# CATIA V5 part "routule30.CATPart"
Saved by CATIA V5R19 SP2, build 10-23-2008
Part number: routule30
Bounding box of the stored display mesh (mm): x 0 to 16, y -31 to 31, z -31 to 31
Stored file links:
  D:\SCHOOL\FRANCE\BANC_POUTRE_EN_MOUSSE\routule30.CATPart
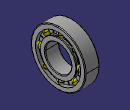
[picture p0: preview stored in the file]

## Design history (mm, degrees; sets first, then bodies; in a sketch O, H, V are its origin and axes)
Body1 "7" (main body)
  Solid1: solid without history
Body2 "6"
  Solid2: solid without history
Body3 "9"
  Solid3: solid without history
Body4 "12"
  Solid4: solid without history
Body5 "1"
  Solid5: solid without history
Body6 "18"
  Solid6: solid without history
Body7 "14"
  Solid7: solid without history
Body8 "3"
  Solid8: solid without history
Body9 "19"
  Solid9: solid without history
Body10 "4"
  Solid10: solid without history
Body11 "2"
  Solid11: solid without history
Body12 "10"
  Solid12: solid without history
Body13 "13"
  Solid13: solid without history
Body14 "8"
  Solid14: solid without history
Body15 "11"
  Solid15: solid without history
Body16 "16"
  Solid16: solid without history
Body17 "17"
  Solid17: solid without history
Body18 "5"
  Solid18: solid without history
Body19 "15"
  Solid19: solid without history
